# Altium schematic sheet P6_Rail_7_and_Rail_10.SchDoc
size 368 x 228 mm
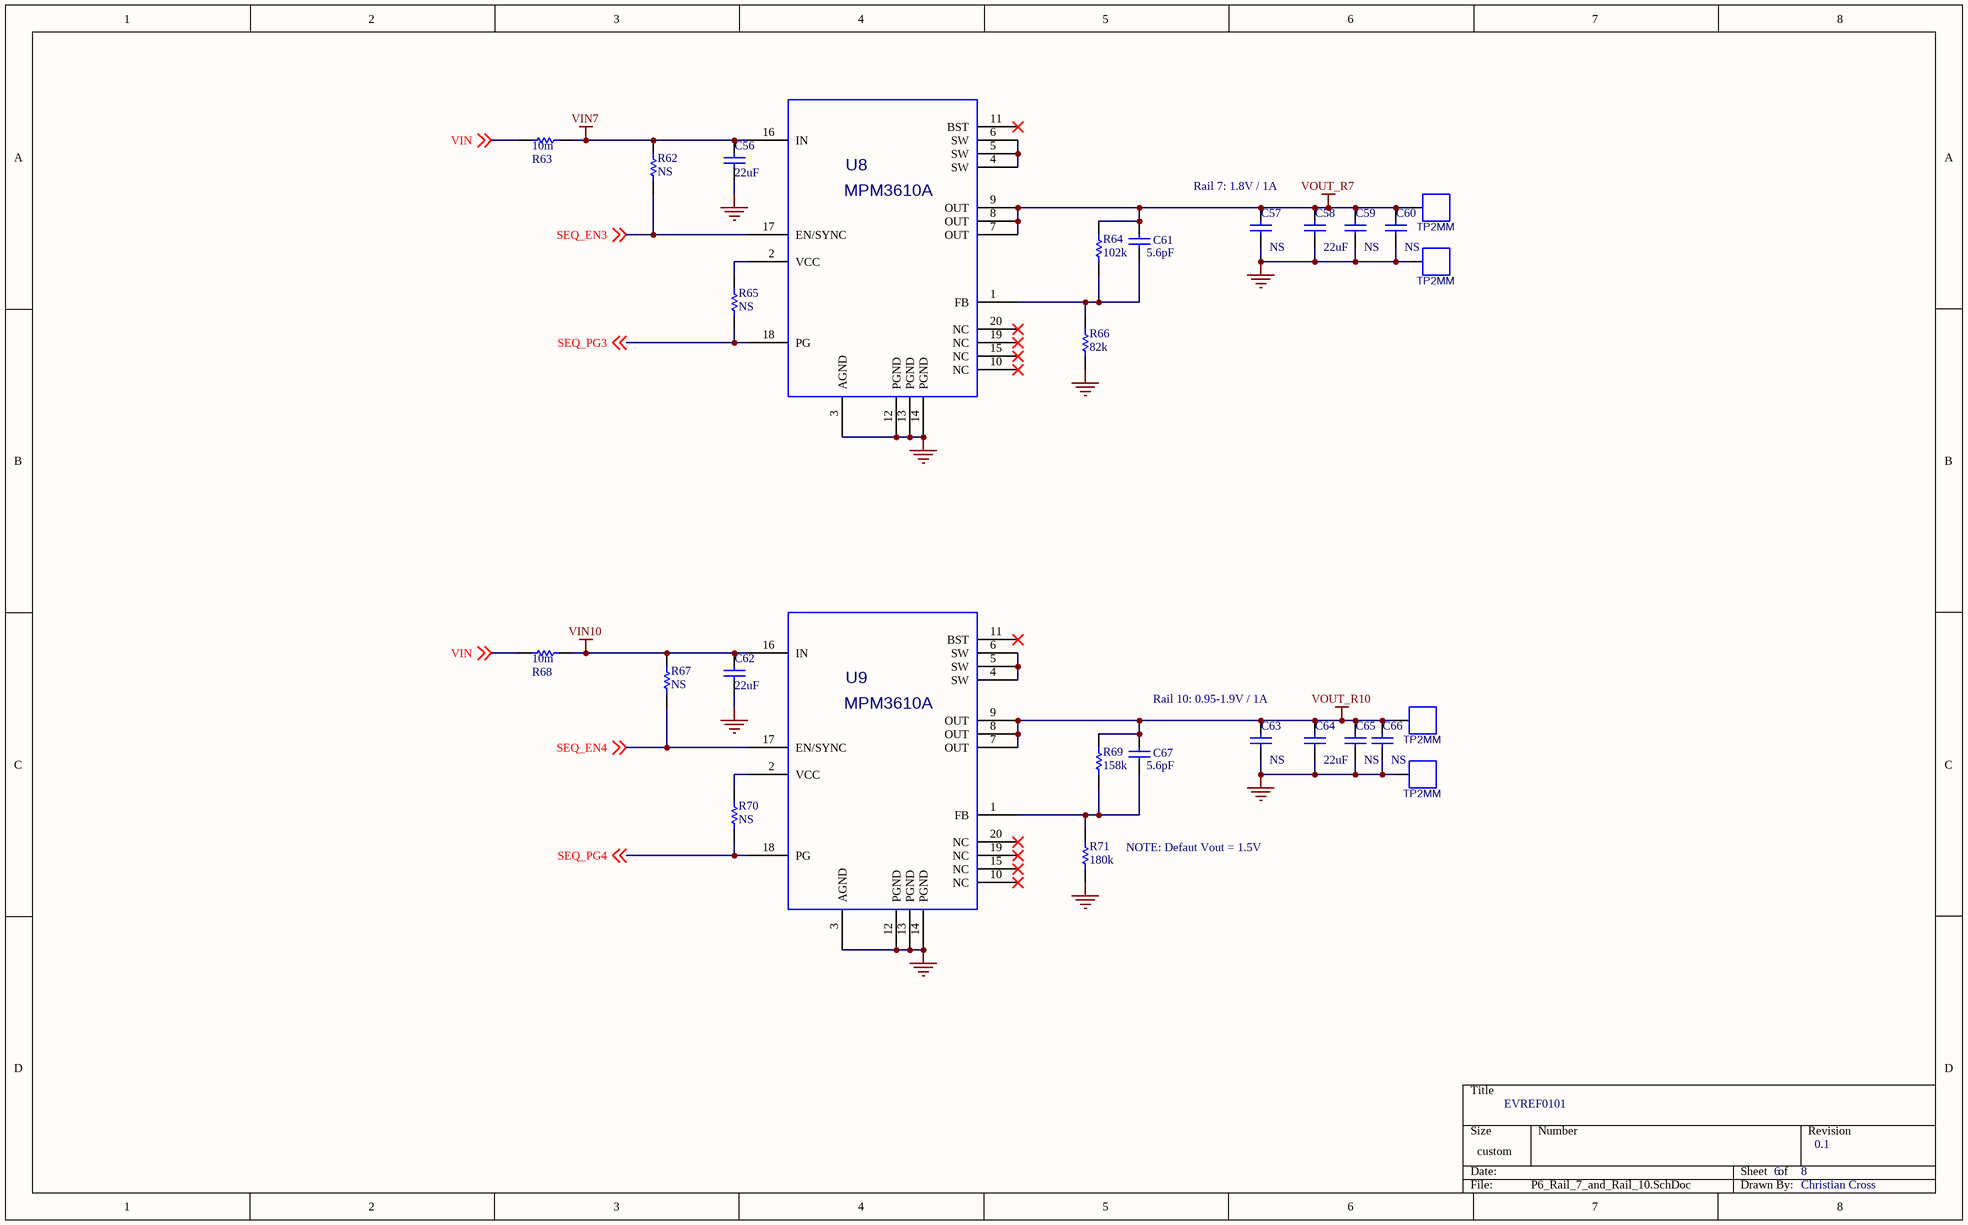
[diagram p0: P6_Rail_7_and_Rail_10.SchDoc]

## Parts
C56  22uF  [CAP0805]
C57  NS  [CAP0805]
C58  22uF  [CAP0805]
C59  NS  [CAP0805]
C60  NS  [CAP0805]
C61  5.6pF  [CAP/0603]
C62  22uF  [CAP0805]
C63  NS  [CAP0805]
C64  22uF  [CAP0805]
C65  NS  [CAP0805]
C66  NS  [CAP0805]
C67  5.6pF  [CAP/0603]
CN13  TP2MM  [TP2MM]
CN14  TP2MM  [TP2MM]
CN15  TP2MM  [TP2MM]
CN16  TP2MM  [TP2MM]
R62  NS  [RES/0603]
R63  10m  [RES/0805]
R64  102k  [RES/0603]
R65  NS  [RES/0603]
R66  82k  [RES/0603]
R67  NS  [RES/0603]
R68  10m  [RES/0805]
R69  158k  [RES/0603]
R70  NS  [RES/0603]
R71  180k  [RES/0603]
U8  Manufacturer P/N: MPM3610A  [QFN20-3X5MM]  (hidden comment: MPM3630A)
U9  Manufacturer P/N: MPM3610A  [QFN20-3X5MM]  (hidden comment: MPM3630A)

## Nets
GND: C56.1 C57.1 C58.1 C59.1 C60.1 C62.1 C63.1 C64.1 C65.1 C66.1 CN14.1 CN16.1 R66.2 R71.2 U8.3(AGND) U8.12(PGND) U8.13(PGND) U8.14(PGND) U9.3(AGND) U9.12(PGND) U9.13(PGND) U9.14(PGND)
VIN7: C56.2 R62.1 R63.2 U8.16(IN)
VIN10: C62.2 R67.1 R68.2 U9.16(IN)
VOUT_R7: C57.2 C58.2 C59.2 C60.2 C61.2 CN13.1 R64.1 U8.7(OUT) U8.8(OUT) U8.9(OUT)
VOUT_R10: C63.2 C64.2 C65.2 C66.2 C67.2 CN15.1 R69.1 U9.7(OUT) U9.8(OUT) U9.9(OUT)
SEQ_EN3: R62.2 U8.17(EN/SYNC) ; off-sheet SEQ_EN3
SEQ_EN4: R67.2 U9.17(EN/SYNC) ; off-sheet SEQ_EN4
SEQ_PG3: R65.2 U8.18(PG) ; off-sheet SEQ_PG3
SEQ_PG4: R70.2 U9.18(PG) ; off-sheet SEQ_PG4
VIN: R63.1 R68.1 ; off-sheet VIN
NetC61_1: C61.1 R64.2 R66.1 U8.1(FB)
NetC67_1: C67.1 R69.2 R71.1 U9.1(FB)
NetR65_1: R65.1 U8.2(VCC)
NetR70_1: R70.1 U9.2(VCC)
NetU8_4: U8.4(SW) U8.5(SW) U8.6(SW)
NetU9_4: U9.4(SW) U9.5(SW) U9.6(SW)

Not connected (* = marked no-connect by the designer): U8 10(NC)* 11(BST)* 15(NC)* 19(NC)* 20(NC)*; U9 10(NC)* 11(BST)* 15(NC)* 19(NC)* 20(NC)*

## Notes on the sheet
- Rail 7: 1.8V / 1A
- Rail 10: 0.95-1.9V / 1A
- (near R71) NOTE: Defaut Vout = 1.5V
- EVREF0101
- 6
- 8
- 0.1
- Christian Cross

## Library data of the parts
C56-C67 = Cap: Capacitor
CN13-CN16 = TP2MM: {Description}; Manufacturer: {Manufacturer}; Manufacturer P/N: {Manufacturer P/N}
R62 R64-R67 R69-R71 = Res1: Resistor
R63 R68 = Res1: Resistor; Value: 10mohm
U8 U9 = MPM3630A: 18V/3A DC/DC Module Synchronous Step-Down Regulator; Manufacturer: {Manufacturer}; Value: MPM3610A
